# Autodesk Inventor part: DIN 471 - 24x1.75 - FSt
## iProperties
Created: 2006-06
Material: FSt
Description: Sicherungsring
Vendor: Autodesk Inc.
Document SubType Name: Modeling
Standard: DIN 471
Designer: I.Baliuc
Standards Organization: DIN
Language: de-DE
Size Designation: 24 x 1.75
Categories: <MemberInstance Version="R10.0.0"><Categories><Category DisplayName="Wellenteile" InternalName="7f7aeb1f-a693-4053-b835-cee3144e0d98" Mnemonic="SHFT"><Category
Density: 7.85 g/cm^3
Mass: 3.56362 g
Surface Area: 8.55566 cm^2
Volume: 0.453964 cm^3
Abmessung: 24 x 1.75
Author: T.Messerschmitt
Comments: DIN 471 - 24 x 1.75
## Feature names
1. Körper [Extrusion]
